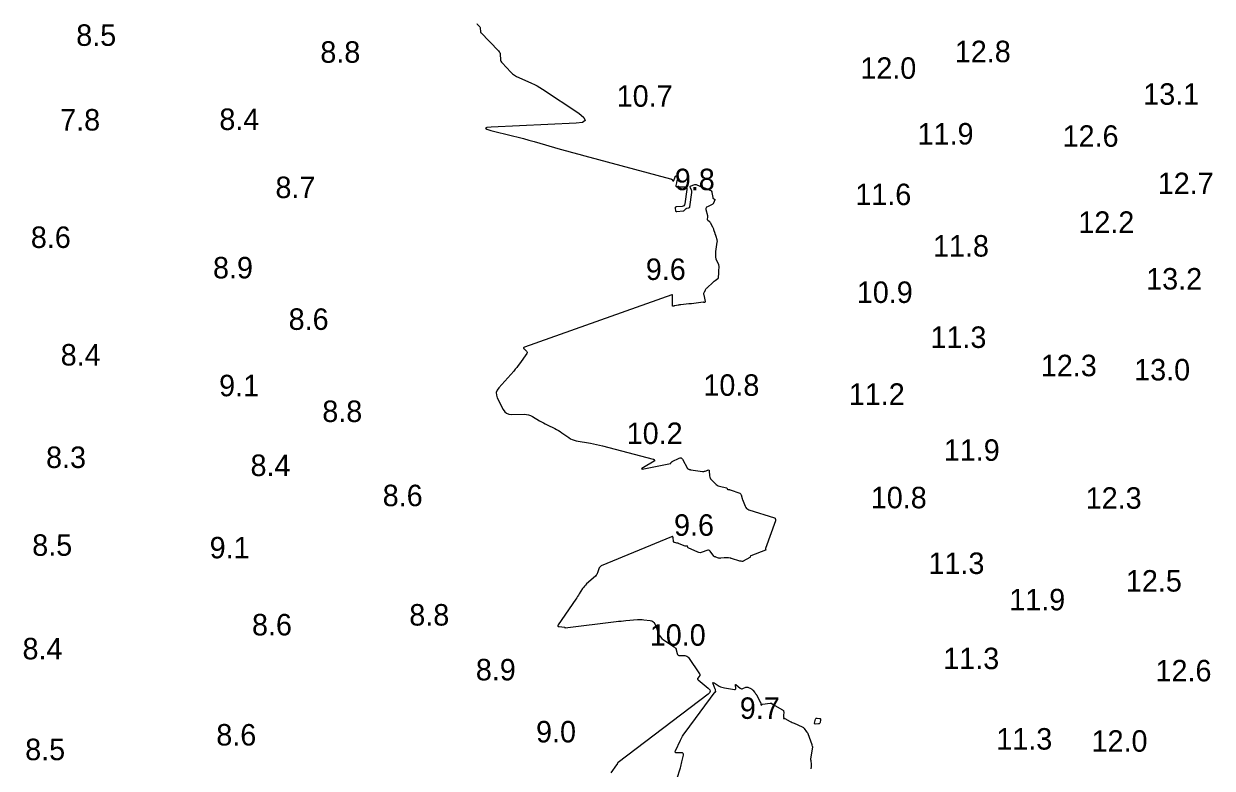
# Model space of a CAD drawing. Extents: x 1023796 to 1112670, y 656573 to 837340.
# Drawn here: x 1100901.1 to 1101177.6, y 687858.4 to 688031.7 of the extents above; entities that cross this region are included whole.
import ezdxf

# ---------------------------------------------------------------- set-up
doc = ezdxf.new("R2010")
doc.units = 0
doc.layers.add('V-CHAN-CONT-10FT', color=7, linetype='Continuous')
doc.layers.add('V-TOPO-SOUN', color=7, linetype='Continuous')

msp = doc.modelspace()

# ---------------------------------------------------------------- linework, layer by layer
at = {"layer": 'V-CHAN-CONT-10FT'}
for points in [[(1101006.5, 688031.73), (1101006.56, 688031.61), (1101006.65, 688031.5), (1101007.09, 688031.02), (1101007.16, 688030.93), (1101007.22, 688030.83), (1101007.25, 688030.72), (1101007.27, 688030.6), (1101007.33, 688029.94), (1101007.33, 688029.91), (1101007.33, 688029.89), (1101007.33, 688029.86), (1101007.34, 688029.83), (1101007.34, 688029.73), (1101007.35, 688029.7), (1101007.35, 688029.68), (1101007.37, 688029.66), (1101007.38, 688029.64), (1101011.52, 688025.37), (1101011.67, 688025.18), (1101011.79, 688024.96), (1101011.87, 688024.73), (1101011.9, 688024.48), (1101011.96, 688023.45), (1101012, 688023.2), (1101012.07, 688022.97), (1101012.19, 688022.75), (1101012.35, 688022.56), (1101014.36, 688020.43), (1101014.77, 688020.04), (1101015.21, 688019.69), (1101015.69, 688019.39), (1101016.2, 688019.14), (1101019.17, 688017.84), (1101019.84, 688017.53), (1101020.48, 688017.2), (1101021.12, 688016.83), (1101021.73, 688016.44), (1101030.22, 688010.83), (1101031.39, 688009.88), (1101031.67, 688009.18), (1101031.07, 688008.72), (1101029.58, 688008.51), (1101009.77, 688007.6), (1101008.79, 688007.51), (1101008.45, 688007.36), (1101008.75, 688007.14), (1101009.7, 688006.86), (1101014.77, 688005.6), (1101016.04, 688005.28), (1101017.3, 688004.95), (1101018.57, 688004.61), (1101019.82, 688004.26), (1101025.87, 688002.52), (1101027.3, 688002.12), (1101028.73, 688001.72), (1101030.16, 688001.32), (1101031.6, 688000.93), (1101051.5, 687995.59), (1101051.59, 687995.56), (1101051.67, 687995.52), (1101051.75, 687995.47), (1101051.82, 687995.41), (1101052.09, 687995.15), (1101052.16, 687995.1), (1101052.21, 687995.09), (1101052.26, 687995.13), (1101052.29, 687995.2), (1101052.57, 687996.04), (1101052.6, 687996.12), (1101052.66, 687996.18), (1101052.73, 687996.22), (1101052.82, 687996.24), (1101053.2, 687996.27), (1101053.28, 687996.27), (1101053.33, 687996.24), (1101053.35, 687996.19), (1101053.33, 687996.11), (1101053.06, 687995.28), (1101053.01, 687995.13), (1101052.97, 687994.97), (1101052.93, 687994.81), (1101052.9, 687994.65), (1101052.77, 687994.02), (1101052.76, 687993.88), (1101052.8, 687993.78), (1101052.89, 687993.72), (1101053.03, 687993.71), (1101054.75, 687993.75), (1101055.04, 687993.71), (1101055.23, 687993.59), (1101055.33, 687993.38), (1101055.33, 687993.09), (1101054.82, 687989.74), (1101054.75, 687989.5), (1101054.63, 687989.33), (1101054.45, 687989.21), (1101054.21, 687989.16), (1101052.85, 687989.03), (1101052.75, 687989), (1101052.68, 687988.95), (1101052.64, 687988.87), (1101052.64, 687988.77), (1101052.68, 687988.14), (1101052.69, 687988.11), (1101052.7, 687988.09), (1101052.72, 687988.06), (1101052.74, 687988.04), (1101052.85, 687987.97), (1101052.88, 687987.96), (1101052.91, 687987.95), (1101052.94, 687987.95), (1101052.97, 687987.95), (1101054.5, 687988.1), (1101054.59, 687988.11), (1101054.66, 687988.14), (1101054.73, 687988.19), (1101054.79, 687988.25), (1101055.01, 687988.54), (1101055.07, 687988.6), (1101055.13, 687988.65), (1101055.21, 687988.69), (1101055.29, 687988.72), (1101055.77, 687988.83), (1101055.86, 687988.87), (1101055.94, 687988.92), (1101055.99, 687989), (1101056.02, 687989.1), (1101056.51, 687992.37), (1101056.52, 687992.52), (1101056.51, 687992.67), (1101056.47, 687992.82), (1101056.42, 687992.96), (1101056.14, 687993.52), (1101056.09, 687993.65), (1101056.1, 687993.76), (1101056.17, 687993.85), (1101056.29, 687993.92), (1101056.98, 687994.2), (1101057.15, 687994.25), (1101057.31, 687994.26), (1101057.47, 687994.25), (1101057.64, 687994.2), (1101058.7, 687993.75), (1101058.94, 687993.65), (1101059.17, 687993.56), (1101059.41, 687993.46), (1101059.64, 687993.38), (1101060.69, 687992.98), (1101060.87, 687992.89), (1101061.02, 687992.76), (1101061.11, 687992.59), (1101061.17, 687992.39), (1101061.34, 687991.2), (1101061.36, 687991.14), (1101061.39, 687991.08), (1101061.43, 687991.04), (1101061.49, 687991), (1101061.75, 687990.88), (1101061.8, 687990.85), (1101061.83, 687990.81), (1101061.84, 687990.76), (1101061.82, 687990.69), (1101061.5, 687989.93), (1101061.42, 687989.79), (1101061.33, 687989.67), (1101061.21, 687989.58), (1101061.07, 687989.5), (1101060.09, 687989.1), (1101059.91, 687988.99), (1101059.79, 687988.85), (1101059.75, 687988.67), (1101059.76, 687988.47), (1101060.09, 687987.04), (1101060.11, 687986.94), (1101060.12, 687986.84), (1101060.12, 687986.74), (1101060.12, 687986.64), (1101060.07, 687986.21), (1101060.07, 687986.13), (1101060.09, 687986.05), (1101060.14, 687985.98), (1101060.2, 687985.93), (1101060.51, 687985.72), (1101060.58, 687985.66), (1101060.65, 687985.6), (1101060.7, 687985.53), (1101060.75, 687985.45), (1101061.29, 687984.39), (1101061.36, 687984.24), (1101061.43, 687984.08), (1101061.49, 687983.93), (1101061.54, 687983.76), (1101061.8, 687982.9), (1101061.82, 687982.84), (1101061.84, 687982.79), (1101061.86, 687982.73), (1101061.89, 687982.67), (1101062, 687982.45), (1101062.02, 687982.39), (1101062.04, 687982.33), (1101062.06, 687982.27), (1101062.08, 687982.21), (1101062.29, 687981.44), (1101062.32, 687981.29), (1101062.34, 687981.14), (1101062.34, 687980.98), (1101062.32, 687980.83), (1101062.01, 687978.68), (1101061.99, 687978.54), (1101061.98, 687978.4), (1101061.97, 687978.26), (1101061.97, 687978.12), (1101061.99, 687977.54), (1101062, 687977.4), (1101062.02, 687977.26), (1101062.06, 687977.13), (1101062.1, 687976.99), (1101062.66, 687975.6), (1101062.71, 687975.45), (1101062.74, 687975.29), (1101062.76, 687975.13), (1101062.76, 687974.97), (1101062.72, 687974.32), (1101062.71, 687974.16), (1101062.7, 687974), (1101062.69, 687973.83), (1101062.68, 687973.67), (1101062.6, 687972.55), (1101062.58, 687972.46), (1101062.55, 687972.38), (1101062.5, 687972.3), (1101062.44, 687972.24), (1101062.1, 687971.96), (1101062.05, 687971.92), (1101062, 687971.88), (1101061.95, 687971.84), (1101061.89, 687971.81), (1101061.66, 687971.68), (1101061.61, 687971.65), (1101061.55, 687971.61), (1101061.5, 687971.57), (1101061.45, 687971.53), (1101059.94, 687970.12), (1101059.83, 687970.02), (1101059.74, 687969.9), (1101059.66, 687969.79), (1101059.59, 687969.66), (1101059.32, 687969.14), (1101059.26, 687969.01), (1101059.23, 687968.87), (1101059.22, 687968.73), (1101059.24, 687968.59), (1101059.55, 687967.02), (1101059.55, 687967), (1101059.55, 687966.97), (1101059.54, 687966.95), (1101059.53, 687966.92), (1101059.48, 687966.82), (1101059.47, 687966.8), (1101059.45, 687966.79), (1101059.43, 687966.79), (1101059.4, 687966.79), (1101059.28, 687966.83), (1101059.25, 687966.83), (1101059.21, 687966.84), (1101059.18, 687966.84), (1101059.15, 687966.84), (1101056.43, 687966.5), (1101056.37, 687966.49), (1101056.32, 687966.49), (1101056.27, 687966.48), (1101056.21, 687966.48), (1101056, 687966.47), (1101055.94, 687966.47), (1101055.89, 687966.47), (1101055.83, 687966.46), (1101055.78, 687966.46), (1101053.95, 687966.27), (1101053.79, 687966.25), (1101053.64, 687966.23), (1101053.48, 687966.2), (1101053.33, 687966.17), (1101052.51, 687966.01), (1101052.45, 687966), (1101052.4, 687965.99), (1101052.35, 687965.97), (1101052.3, 687965.96), (1101052.1, 687965.91), (1101052.05, 687965.91), (1101052.02, 687965.92), (1101052, 687965.95), (1101051.99, 687965.99), (1101051.98, 687967.82), (1101051.98, 687967.9), (1101051.98, 687967.98), (1101051.98, 687968.06), (1101051.99, 687968.14), (1101052, 687968.46), (1101051.99, 687968.52), (1101051.96, 687968.56), (1101051.92, 687968.58), (1101051.85, 687968.56), (1101017.52, 687956.37), (1101017.38, 687956.3), (1101017.32, 687956.21), (1101017.34, 687956.1), (1101017.44, 687955.98), (1101018.02, 687955.47), (1101018.13, 687955.34), (1101018.18, 687955.2), (1101018.16, 687955.05), (1101018.08, 687954.9), (1101016.41, 687952.54), (1101016.09, 687952.1), (1101015.75, 687951.67), (1101015.41, 687951.25), (1101015.05, 687950.84), (1101011.55, 687946.94), (1101011.16, 687946.39), (1101010.98, 687945.81), (1101011.01, 687945.21), (1101011.23, 687944.57), (1101012.59, 687941.88), (1101012.94, 687941.36), (1101013.38, 687941), (1101013.91, 687940.78), (1101014.53, 687940.72), (1101017.53, 687940.78), (1101018.02, 687940.76), (1101018.49, 687940.67), (1101018.94, 687940.51), (1101019.38, 687940.28), (1101021.08, 687939.24), (1101021.51, 687938.99), (1101021.94, 687938.75), (1101022.37, 687938.52), (1101022.81, 687938.3), (1101024.6, 687937.43), (1101025.03, 687937.21), (1101025.45, 687936.98), (1101025.86, 687936.73), (1101026.26, 687936.46), (1101027.84, 687935.35), (1101028.25, 687935.09), (1101028.67, 687934.89), (1101029.12, 687934.73), (1101029.59, 687934.63), (1101032.9, 687934.04), (1101033.61, 687933.91), (1101034.31, 687933.76), (1101035.02, 687933.6), (1101035.72, 687933.43), (1101047.46, 687930.35), (1101047.52, 687930.33), (1101047.57, 687930.3), (1101047.61, 687930.27), (1101047.65, 687930.22), (1101047.78, 687930.01), (1101047.8, 687929.96), (1101047.8, 687929.92), (1101047.78, 687929.88), (1101047.74, 687929.85), (1101045.21, 687928.4), (1101044.88, 687928.19), (1101044.8, 687928.07), (1101044.94, 687928.03), (1101045.32, 687928.09), (1101051.52, 687929.29), (1101051.56, 687929.3), (1101051.59, 687929.32), (1101051.61, 687929.35), (1101051.63, 687929.39), (1101051.69, 687929.58), (1101051.7, 687929.6), (1101051.72, 687929.62), (1101051.73, 687929.64), (1101051.75, 687929.65), (1101051.83, 687929.71), (1101051.85, 687929.73), (1101051.87, 687929.74), (1101051.9, 687929.75), (1101051.92, 687929.76), (1101053.51, 687930.55), (1101053.76, 687930.63), (1101053.99, 687930.62), (1101054.18, 687930.5), (1101054.34, 687930.29), (1101055.49, 687928.17), (1101055.51, 687928.15), (1101055.53, 687928.13), (1101055.55, 687928.11), (1101055.57, 687928.09), (1101055.68, 687928.02), (1101055.7, 687928.01), (1101055.72, 687928), (1101055.74, 687927.98), (1101055.76, 687927.97), (1101055.83, 687927.92), (1101055.85, 687927.91), (1101055.87, 687927.9), (1101055.9, 687927.89), (1101055.92, 687927.89), (1101056.12, 687927.89), (1101056.16, 687927.89), (1101056.2, 687927.88), (1101056.24, 687927.88), (1101056.28, 687927.87), (1101058.99, 687927.47), (1101059.15, 687927.46), (1101059.3, 687927.47), (1101059.46, 687927.5), (1101059.6, 687927.55), (1101060.19, 687927.79), (1101060.32, 687927.83), (1101060.42, 687927.8), (1101060.48, 687927.73), (1101060.51, 687927.6), (1101060.62, 687926.41), (1101060.66, 687926.17), (1101060.75, 687925.95), (1101060.86, 687925.74), (1101061.02, 687925.56), (1101061.93, 687924.63), (1101062.15, 687924.44), (1101062.39, 687924.28), (1101062.64, 687924.15), (1101062.92, 687924.06), (1101064.56, 687923.62), (1101064.59, 687923.6), (1101064.62, 687923.58), (1101064.65, 687923.56), (1101064.67, 687923.53), (1101064.74, 687923.38), (1101064.75, 687923.35), (1101064.78, 687923.33), (1101064.81, 687923.31), (1101064.85, 687923.3), (1101065.18, 687923.25), (1101065.24, 687923.23), (1101065.31, 687923.22), (1101065.38, 687923.2), (1101065.44, 687923.18), (1101067.62, 687922.42), (1101067.74, 687922.36), (1101067.84, 687922.28), (1101067.91, 687922.18), (1101067.96, 687922.05), (1101068.11, 687921.5), (1101068.14, 687921.36), (1101068.19, 687921.22), (1101068.23, 687921.09), (1101068.28, 687920.95), (1101068.9, 687919.36), (1101069.04, 687919.08), (1101069.24, 687918.85), (1101069.48, 687918.67), (1101069.77, 687918.55), (1101075.72, 687916.69), (1101075.78, 687916.66), (1101075.83, 687916.62), (1101075.87, 687916.57), (1101075.89, 687916.51), (1101075.96, 687916.25), (1101075.97, 687916.18), (1101075.98, 687916.11), (1101075.97, 687916.05), (1101075.95, 687915.98), (1101073.63, 687909.51), (1101073.63, 687909.48), (1101073.62, 687909.44), (1101073.62, 687909.41), (1101073.63, 687909.37), (1101073.67, 687909.23), (1101073.67, 687909.2), (1101073.67, 687909.18), (1101073.65, 687909.16), (1101073.62, 687909.14), (1101070.21, 687907.86), (1101070.18, 687907.85), (1101070.15, 687907.82), (1101070.13, 687907.79), (1101070.12, 687907.75), (1101070.08, 687907.59), (1101070.07, 687907.55), (1101070.05, 687907.52), (1101070.02, 687907.49), (1101069.99, 687907.47), (1101068.46, 687906.59), (1101068.4, 687906.56), (1101068.34, 687906.54), (1101068.28, 687906.53), (1101068.21, 687906.53), (1101067.94, 687906.56), (1101067.88, 687906.57), (1101067.81, 687906.58), (1101067.75, 687906.6), (1101067.68, 687906.61), (1101065.69, 687907.21), (1101065.62, 687907.23), (1101065.54, 687907.25), (1101065.46, 687907.27), (1101065.38, 687907.28), (1101065.05, 687907.33), (1101064.97, 687907.35), (1101064.89, 687907.35), (1101064.81, 687907.36), (1101064.73, 687907.36), (1101064.34, 687907.35), (1101064.25, 687907.35), (1101064.16, 687907.34), (1101064.07, 687907.33), (1101063.98, 687907.33), (1101063.19, 687907.25), (1101063.06, 687907.24), (1101062.94, 687907.25), (1101062.82, 687907.27), (1101062.71, 687907.3), (1101062.09, 687907.51), (1101062.05, 687907.53), (1101062, 687907.54), (1101061.96, 687907.56), (1101061.91, 687907.57), (1101061.73, 687907.63), (1101061.69, 687907.65), (1101061.65, 687907.67), (1101061.61, 687907.7), (1101061.58, 687907.74), (1101060.73, 687908.88), (1101060.56, 687909.05), (1101060.38, 687909.14), (1101060.18, 687909.15), (1101059.95, 687909.1), (1101058.9, 687908.66), (1101058.64, 687908.59), (1101058.39, 687908.56), (1101058.14, 687908.6), (1101057.89, 687908.68), (1101055.66, 687909.68), (1101055.62, 687909.7), (1101055.58, 687909.74), (1101055.56, 687909.78), (1101055.55, 687909.83), (1101055.51, 687910.03), (1101055.49, 687910.08), (1101055.47, 687910.1), (1101055.43, 687910.12), (1101055.38, 687910.11), (1101055.16, 687910.05), (1101055.1, 687910.05), (1101055.05, 687910.04), (1101055, 687910.05), (1101054.94, 687910.07), (1101053.52, 687910.65), (1101053.4, 687910.7), (1101053.27, 687910.74), (1101053.15, 687910.77), (1101053.02, 687910.8), (1101052.5, 687910.9), (1101052.39, 687910.94), (1101052.3, 687911.01), (1101052.25, 687911.1), (1101052.22, 687911.22), (1101052.14, 687912.05), (1101052.1, 687912.21), (1101052.02, 687912.29), (1101051.91, 687912.32), (1101051.76, 687912.28), (1101035.4, 687905.48), (1101035.2, 687905.37), (1101035.04, 687905.22), (1101034.91, 687905.04), (1101034.83, 687904.83), (1101034.57, 687903.9), (1101034.49, 687903.68), (1101034.39, 687903.47), (1101034.25, 687903.29), (1101034.08, 687903.12), (1101031.98, 687901.28), (1101031.72, 687901.03), (1101031.48, 687900.77), (1101031.26, 687900.49), (1101031.05, 687900.19), (1101030.28, 687898.96), (1101030.09, 687898.66), (1101029.89, 687898.36), (1101029.69, 687898.05), (1101029.49, 687897.75), (1101025.41, 687891.77), (1101025.32, 687891.61), (1101025.33, 687891.49), (1101025.42, 687891.41), (1101025.6, 687891.36), (1101026.88, 687891.24), (1101026.9, 687891.23), (1101026.91, 687891.23), (1101026.92, 687891.21), (1101026.92, 687891.2), (1101026.93, 687891.12), (1101026.94, 687891.11), (1101026.95, 687891.1), (1101026.96, 687891.09), (1101026.98, 687891.09), (1101038.88, 687892.51), (1101039.45, 687892.58), (1101040.02, 687892.64), (1101040.59, 687892.7), (1101041.16, 687892.75), (1101043.82, 687892.97), (1101044.2, 687892.99), (1101044.57, 687893), (1101044.94, 687892.98), (1101045.32, 687892.95), (1101046.81, 687892.8), (1101047.16, 687892.72), (1101047.44, 687892.56), (1101047.67, 687892.33), (1101047.84, 687892.02), (1101048.69, 687889.84), (1101048.91, 687889.39), (1101049.18, 687888.98), (1101049.52, 687888.62), (1101049.92, 687888.3), (1101052.39, 687886.61), (1101052.55, 687886.47), (1101052.69, 687886.31), (1101052.8, 687886.13), (1101052.87, 687885.93), (1101053.1, 687885.06), (1101053.18, 687884.88), (1101053.3, 687884.74), (1101053.46, 687884.66), (1101053.67, 687884.62), (1101054.85, 687884.6), (1101055.11, 687884.57), (1101055.34, 687884.48), (1101055.53, 687884.34), (1101055.7, 687884.14), (1101058.3, 687880.34), (1101058.31, 687880.31), (1101058.32, 687880.28), (1101058.33, 687880.25), (1101058.34, 687880.23), (1101058.35, 687880.11), (1101058.35, 687880.08), (1101058.35, 687880.05), (1101058.34, 687880.02), (1101058.32, 687880), (1101057.88, 687879.35), (1101057.83, 687879.24), (1101057.82, 687879.13), (1101057.86, 687879.04), (1101057.94, 687878.94), (1101060.31, 687877.01), (1101060.64, 687876.66), (1101060.74, 687876.31), (1101060.62, 687875.97), (1101060.29, 687875.63), (1101039.31, 687859.75), (1101039.27, 687859.71), (1101039.23, 687859.67), (1101039.2, 687859.62), (1101039.18, 687859.57), (1101039.1, 687859.35), (1101039.08, 687859.29), (1101039.05, 687859.24), (1101039.02, 687859.19), (1101038.99, 687859.14), (1101037.65, 687857.32)], [(1101052.99, 687855.87), (1101053.81, 687858.46), (1101053.91, 687858.81), (1101054.01, 687859.15), (1101054.09, 687859.5), (1101054.17, 687859.85), (1101054.51, 687861.44), (1101054.53, 687861.67), (1101054.46, 687861.84), (1101054.31, 687861.94), (1101054.08, 687861.97), (1101052.98, 687861.97), (1101052.76, 687862), (1101052.63, 687862.1), (1101052.6, 687862.25), (1101052.67, 687862.47), (1101053.81, 687864.89), (1101054.05, 687865.36), (1101054.31, 687865.83), (1101054.59, 687866.28), (1101054.9, 687866.72), (1101061.89, 687876.15), (1101061.9, 687876.16), (1101061.92, 687876.17), (1101061.93, 687876.18), (1101061.95, 687876.18), (1101062.02, 687876.19), (1101062.03, 687876.19), (1101062.04, 687876.2), (1101062.05, 687876.21), (1101062.05, 687876.23), (1101062.01, 687876.54), (1101062, 687876.6), (1101061.99, 687876.65), (1101061.97, 687876.71), (1101061.95, 687876.76), (1101061.42, 687878.02), (1101061.37, 687878.21), (1101061.39, 687878.3), (1101061.48, 687878.31), (1101061.66, 687878.23), (1101062.88, 687877.51), (1101063.16, 687877.37), (1101063.45, 687877.25), (1101063.75, 687877.16), (1101064.06, 687877.09), (1101066.42, 687876.72), (1101066.57, 687876.72), (1101066.66, 687876.77), (1101066.71, 687876.86), (1101066.71, 687877.01), (1101066.61, 687877.7), (1101066.61, 687877.83), (1101066.64, 687877.9), (1101066.71, 687877.89), (1101066.82, 687877.81), (1101067.73, 687877.03), (1101067.87, 687876.93), (1101068.02, 687876.88), (1101068.18, 687876.88), (1101068.34, 687876.92), (1101069.08, 687877.22), (1101069.22, 687877.26), (1101069.36, 687877.27), (1101069.5, 687877.25), (1101069.63, 687877.2), (1101070.18, 687876.95), (1101070.31, 687876.88), (1101070.43, 687876.8), (1101070.54, 687876.7), (1101070.64, 687876.59), (1101071.11, 687876.02), (1101071.22, 687875.88), (1101071.32, 687875.74), (1101071.42, 687875.59), (1101071.5, 687875.44), (1101072.48, 687873.66), (1101072.5, 687873.63), (1101072.51, 687873.6), (1101072.52, 687873.57), (1101072.52, 687873.54), (1101072.54, 687873.41), (1101072.54, 687873.37), (1101072.55, 687873.34), (1101072.55, 687873.31), (1101072.55, 687873.27), (1101072.58, 687873.05), (1101072.58, 687873.03), (1101072.59, 687873.03), (1101072.6, 687873.02), (1101072.61, 687873.02), (1101072.68, 687873.04), (1101072.69, 687873.05), (1101072.7, 687873.05), (1101072.71, 687873.07), (1101072.72, 687873.08), (1101072.81, 687873.21), (1101072.83, 687873.23), (1101072.85, 687873.25), (1101072.88, 687873.27), (1101072.91, 687873.27), (1101074.74, 687873.55), (1101074.84, 687873.56), (1101074.93, 687873.54), (1101075.02, 687873.51), (1101075.1, 687873.46), (1101075.42, 687873.22), (1101075.51, 687873.16), (1101075.59, 687873.1), (1101075.67, 687873.05), (1101075.76, 687873), (1101077.55, 687872.01), (1101077.68, 687871.92), (1101077.78, 687871.81), (1101077.83, 687871.67), (1101077.85, 687871.51), (1101077.84, 687870.55), (1101077.84, 687870.52), (1101077.84, 687870.49), (1101077.84, 687870.45), (1101077.84, 687870.42), (1101077.85, 687870.28), (1101077.85, 687870.25), (1101077.85, 687870.22), (1101077.84, 687870.19), (1101077.84, 687870.16), (1101077.8, 687870.05), (1101077.8, 687870.02), (1101077.81, 687870), (1101077.82, 687869.99), (1101077.85, 687869.99), (1101078, 687869.98), (1101078.03, 687869.98), (1101078.07, 687869.98), (1101078.1, 687869.97), (1101078.13, 687869.95), (1101079.39, 687869.28), (1101079.61, 687869.16), (1101079.84, 687869.05), (1101080.06, 687868.94), (1101080.29, 687868.84), (1101082.16, 687868), (1101082.3, 687867.92), (1101082.43, 687867.83), (1101082.55, 687867.72), (1101082.65, 687867.6), (1101083.2, 687866.88), (1101083.22, 687866.85), (1101083.25, 687866.81), (1101083.27, 687866.78), (1101083.3, 687866.74), (1101083.4, 687866.61), (1101083.42, 687866.58), (1101083.44, 687866.54), (1101083.46, 687866.5), (1101083.48, 687866.46), (1101084.38, 687863.94), (1101084.4, 687863.89), (1101084.41, 687863.83), (1101084.43, 687863.78), (1101084.44, 687863.73), (1101084.51, 687863.44), (1101084.52, 687863.43), (1101084.52, 687863.41), (1101084.53, 687863.4), (1101084.54, 687863.39), (1101084.57, 687863.34), (1101084.58, 687863.33), (1101084.58, 687863.32), (1101084.59, 687863.3), (1101084.58, 687863.29), (1101084.18, 687861.01), (1101084.15, 687860.81), (1101084.13, 687860.62), (1101084.13, 687860.42), (1101084.14, 687860.22), (1101084.23, 687859.27), (1101084.24, 687859.15), (1101084.24, 687859.02), (1101084.23, 687858.89), (1101084.22, 687858.77), (1101084.14, 687858.26)]]:
    msp.add_lwpolyline(points, dxfattribs=at)
msp.add_lwpolyline([(1101086.22, 687868.81), (1101086.12, 687868.75), (1101085.99, 687868.72), (1101085.19, 687868.63), (1101085.16, 687868.63), (1101085.13, 687868.64), (1101085.11, 687868.65), (1101085.09, 687868.68), (1101085.02, 687868.77), (1101085.01, 687868.8), (1101085, 687868.82), (1101085, 687868.85), (1101085, 687868.88), (1101085.25, 687869.81), (1101085.3, 687869.93), (1101085.38, 687870.01), (1101085.48, 687870.06), (1101085.62, 687870.06), (1101086.19, 687869.98), (1101086.31, 687869.95), (1101086.39, 687869.89), (1101086.43, 687869.79), (1101086.43, 687869.66), (1101086.33, 687869.03), (1101086.29, 687868.91)], close=True, dxfattribs=at)

# ---------------------------------------------------------------- texts
at = {"layer": 'V-TOPO-SOUN'}
for s, p in [('8.5', (1100913.26, 688026.53)), ('8.8', (1100970.05, 688022.6)), ('12.8 ', (1101117.67, 688022.73)), ('12.0 ', (1101095.69, 688018.86)), ('10.7 ', (1101039, 688012.36)), ('13.1 ', (1101161.51, 688012.82)), ('7.8', (1100909.52, 688006.82)), ('8.4', (1100946.56, 688006.95)), ('11.9 ', (1101109.01, 688003.57)), ('12.6 ', (1101142.75, 688003.04)), ('9.8', (1101052.53, 687992.94)), ('8.7', (1100959.61, 687991.1)), ('12.7 ', (1101164.88, 687992.02)), ('11.6 ', (1101094.52, 687989.46)), ('12.2 ', (1101146.41, 687983)), ('8.6', (1100902.7, 687979.49)), ('11.8 ', (1101112.59, 687977.48)), ('8.9', (1100945.08, 687972.4)), ('9.6', (1101045.78, 687972.04)), ('13.2 ', (1101162.19, 687969.81)), ('10.9 ', (1101094.87, 687966.69)), ('8.6', (1100962.68, 687960.42)), ('11.3 ', (1101112, 687956.22)), ('8.4', (1100909.65, 687952.12)), ('12.3 ', (1101137.68, 687949.63)), ('13.0 ', (1101159.4, 687948.65)), ('9.1', (1100946.5, 687944.97)), ('10.8 ', (1101059.17, 687945.07)), ('11.2 ', (1101093, 687942.97)), ('8.8', (1100970.51, 687938.97)), ('10.2 ', (1101041.33, 687933.85)), ('11.9 ', (1101115.11, 687929.94)), ('8.3', (1100906.24, 687928.27)), ('8.4', (1100953.81, 687926.4)), ('8.6', (1100984.56, 687919.38)), ('10.8 ', (1101098.12, 687918.89)), ('12.3 ', (1101148.12, 687918.79)), ('9.6', (1101052.34, 687912.49)), ('8.5', (1100903.02, 687907.83)), ('9.1', (1100944.3, 687907.24)), ('11.3 ', (1101111.54, 687903.6)), ('12.5 ', (1101157.47, 687899.5)), ('11.9 ', (1101130.34, 687895.14)), ('8.8', (1100990.75, 687891.59)), ('8.6', (1100954.15, 687889.3)), ('10.0 ', (1101046.7, 687886.9)), ('8.4', (1100900.76, 687883.72)), ('11.3 ', (1101114.98, 687881.45)), ('8.9', (1101006.23, 687878.83)), ('12.6 ', (1101164.37, 687878.6)), ('9.7', (1101067.65, 687869.87)), ('8.6', (1100945.85, 687863.67)), ('9.0', (1101020.24, 687864.39)), ('11.3 ', (1101127.32, 687862.72)), ('8.5', (1100901.38, 687860.26)), ('12.0 ', (1101149.49, 687862.23))]:
    msp.add_text(s, height=5, dxfattribs=at).set_placement(p)

doc.saveas('drawing.dxf')
